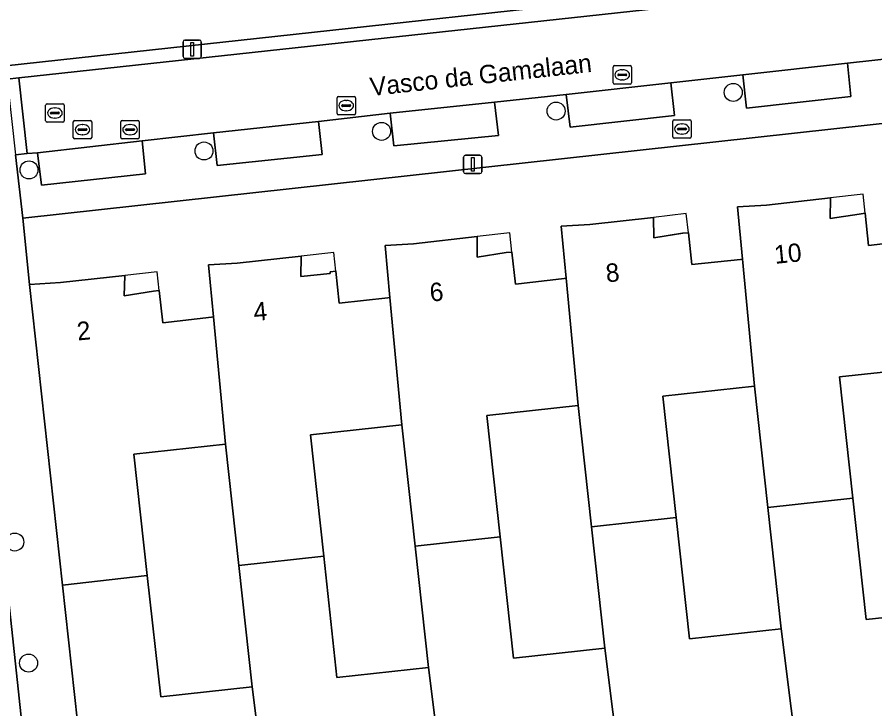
# Model space of a CAD drawing. Extents: x 161248 to 161848, y 384871 to 385383.
# Drawn here: x 161347.65 to 161394.3, y 385074.55 to 385112.17 of the extents above; entities that cross this region are included whole.
import ezdxf

# ---------------------------------------------------------------- set-up
doc = ezdxf.new("R2010")
doc.units = 0
for name, color, linetype in [('IMGEO_Boom', 7, 'Continuous'), ('IMGEO_Brandkraan', 7, 'Continuous'), ('IMGEO_Erf', 7, 'Continuous'), ('IMGEO_Kolk', 7, 'Continuous'), ('IMGEO_Lichtmast', 7, 'Continuous'), ('IMGEO_Openbare_ruimte_label', 7, 'Continuous'), ('IMGEO_Pand', 7, 'Continuous'), ('IMGEO_Pand_nummerreeks', 7, 'Continuous'), ('IMGEO_Pand_overbouw', 7, 'Continuous'), ('IMGEO_Parkeervlak_open', 7, 'Continuous'), ('IMGEO_Rijbaan_lokaal_open', 7, 'Continuous'), ('IMGEO_Rioolput', 7, 'Continuous'), ('IMGEO_Voetpad_open', 7, 'Continuous')]:
    doc.layers.add(name, color=color, linetype=linetype)

msp = doc.modelspace()

# ---------------------------------------------------------------- linework, layer by layer
at = {"layer": 'IMGEO_Boom'}
for centre in [(161386.594, 385108.08), (161376.963, 385107.067), (161367.474, 385105.962), (161357.815, 385104.894), (161348.299, 385103.866), (161347.527, 385083.626), (161348.275, 385077.04)]:
    msp.add_circle(centre, 0.489, dxfattribs=at)
at = {"layer": 'IMGEO_Brandkraan'}
for p, q in [((161383.303, 385105.663), (161383.303, 385106.515)), ((161383.378, 385106.589), (161384.23, 385106.589)), ((161384.304, 385106.515), (161384.304, 385105.663)), ((161383.562, 385106.083), (161383.562, 385106.095)), ((161384, 385106.046), (161383.602, 385106.046)), ((161383.605, 385106.132), (161384.003, 385106.132)), ((161383.791, 385106.369), (161383.816, 385106.369)), ((161384.046, 385106.095), (161384.046, 385106.083)), ((161384.23, 385105.589), (161383.378, 385105.589)), ((161383.814, 385105.809), (161383.789, 385105.809))]:
    msp.add_line(p, q, dxfattribs=at)
for points in [[(161383.303, 385105.663), (161383.303, 385106.515)], [(161383.378, 385106.589), (161384.23, 385106.589)], [(161384.304, 385106.515), (161384.304, 385105.663)], [(161384.23, 385105.589), (161383.378, 385105.589)]]:
    msp.add_lwpolyline(points, dxfattribs=at)
for centre, radius, start, end in [((161383.38, 385106.513), 0.0765, 91.552, 178.448), ((161383.38, 385106.513), 0.0765, 91.552, 178.448), ((161384.228, 385106.513), 0.0765, 1.552, 88.448), ((161384.228, 385106.513), 0.0765, 1.552, 88.448), ((161383.602, 385106.092), 0.0403, 85.8775, 175.7526), ((161383.599, 385106.082), 0.0366, 178.938, 274.7102), ((161384.003, 385106.089), 0.043, 264.8664, 352.4533), ((161384.007, 385106.094), 0.0386, 1.7309, 96.639), ((161383.38, 385105.665), 0.0765, 181.552, 268.448), ((161383.38, 385105.665), 0.0765, 181.552, 268.448), ((161384.228, 385105.665), 0.0765, 271.552, 358.448), ((161384.228, 385105.665), 0.0765, 271.552, 358.448)]:
    msp.add_arc(centre, radius, start, end, dxfattribs=at)
for centre, major_axis, ratio, start_param, end_param in [((161383.79, 385106.089), (-0.387, 0.002), 0.722429, 4.712389, 7.853982), ((161383.815, 385106.089), (-0.39, 0.002), 0.717154, 1.570796, 4.712389)]:
    msp.add_ellipse(centre, major_axis=major_axis, ratio=ratio, start_param=start_param, end_param=end_param, dxfattribs=at)
at = {"layer": 'IMGEO_Erf'}
for points in [[(161346.621, 385113.155), (161347.043, 385109.527), (161395.24, 385114.796)], [(161396.177, 385106.561), (161347.958, 385101.247), (161348.324, 385097.628), (161350.02, 385097.735), (161353.505, 385098.125), (161353.479, 385097.007), (161355.064, 385097.262), (161355.384, 385097.3), (161355.582, 385095.542), (161358.216, 385095.855), (161358.329, 385095.868), (161358.064, 385098.701), (161359.617, 385098.791), (161363.102, 385099.18), (161363.085, 385098.066), (161364.68, 385098.223), (161364.67, 385098.325), (161364.982, 385098.356), (161365.171, 385096.619), (161367.817, 385096.913), (161367.93, 385096.926), (161367.668, 385099.753), (161369.2, 385099.839), (161372.675, 385100.238), (161372.675, 385100.219), (161372.674, 385099.12), (161374.239, 385099.377), (161374.563, 385099.398), (161374.763, 385097.649), (161374.919, 385097.667), (161377.249, 385097.943), (161377.398, 385097.961), (161377.511, 385097.974), (161377.246, 385100.811), (161378.806, 385100.893), (161382.257, 385101.285), (161382.274, 385100.174), (161383.835, 385100.418), (161384.156, 385100.449), (161384.347, 385098.716), (161386.986, 385099.001), (161387.099, 385099.013), (161386.833, 385101.856), (161388.402, 385101.946), (161391.885, 385102.341), (161391.863, 385101.222), (161393.446, 385101.462), (161393.768, 385101.507), (161393.957, 385099.746), (161396.893, 385100.095)]]:
    msp.add_lwpolyline(points, dxfattribs=at)
for points in [[(161397.643, 385093.177), (161392.383, 385092.607), (161393.106, 385086.007), (161393.83, 385079.404), (161399.089, 385079.976)], [(161387.745, 385092.1), (161382.774, 385091.556), (161383.499, 385084.956), (161384.225, 385078.353), (161389.196, 385078.897), (161388.471, 385085.497)], [(161378.883, 385084.458), (161378.158, 385091.05), (161373.188, 385090.506), (161373.914, 385083.906), (161374.64, 385077.304), (161379.61, 385077.848)], [(161368.572, 385090.002), (161363.603, 385089.458), (161364.324, 385082.857), (161365.046, 385076.254), (161370.015, 385076.798), (161369.294, 385083.399)], [(161354.733, 385081.808), (161355.46, 385075.205), (161360.431, 385075.749), (161359.704, 385082.348), (161358.976, 385088.951), (161354.006, 385088.408)]]:
    msp.add_lwpolyline(points, close=True, dxfattribs=at)
at = {"layer": 'IMGEO_Kolk'}
for p, q in [((161380.058, 385108.61), (161380.058, 385109.462)), ((161380.133, 385109.536), (161380.985, 385109.536)), ((161380.546, 385109.316), (161380.571, 385109.316)), ((161381.059, 385109.462), (161381.059, 385108.61)), ((161380.317, 385109.03), (161380.317, 385109.042)), ((161380.755, 385108.993), (161380.357, 385108.993)), ((161380.36, 385109.079), (161380.758, 385109.079)), ((161380.801, 385109.042), (161380.801, 385109.03)), ((161380.985, 385108.536), (161380.133, 385108.536)), ((161380.569, 385108.756), (161380.544, 385108.756)), ((161365.048, 385106.937), (161365.048, 385107.789)), ((161365.123, 385107.863), (161365.975, 385107.863)), ((161365.536, 385107.643), (161365.561, 385107.643)), ((161366.049, 385107.789), (161366.049, 385106.937)), ((161365.307, 385107.357), (161365.307, 385107.369)), ((161365.745, 385107.32), (161365.347, 385107.32)), ((161365.35, 385107.406), (161365.748, 385107.406)), ((161365.559, 385107.083), (161365.534, 385107.083)), ((161365.791, 385107.369), (161365.791, 385107.357)), ((161353.371, 385106.555), (161354.223, 385106.555)), ((161365.975, 385106.863), (161365.123, 385106.863)), ((161353.296, 385105.629), (161353.296, 385106.481)), ((161353.555, 385106.049), (161353.555, 385106.061)), ((161353.598, 385106.098), (161353.996, 385106.098)), ((161353.784, 385106.335), (161353.809, 385106.335)), ((161354.039, 385106.061), (161354.039, 385106.049)), ((161354.297, 385106.481), (161354.297, 385105.629)), ((161354.223, 385105.555), (161353.371, 385105.555)), ((161353.993, 385106.012), (161353.595, 385106.012)), ((161353.807, 385105.775), (161353.782, 385105.775))]:
    msp.add_line(p, q, dxfattribs=at)
for points in [[(161380.058, 385108.61), (161380.058, 385109.462)], [(161380.133, 385109.536), (161380.985, 385109.536)], [(161381.059, 385109.462), (161381.059, 385108.61)], [(161380.985, 385108.536), (161380.133, 385108.536)], [(161365.048, 385106.937), (161365.048, 385107.789)], [(161365.123, 385107.863), (161365.975, 385107.863)], [(161366.049, 385107.789), (161366.049, 385106.937)], [(161353.371, 385106.555), (161354.223, 385106.555)], [(161365.975, 385106.863), (161365.123, 385106.863)], [(161353.296, 385105.629), (161353.296, 385106.481)], [(161354.297, 385106.481), (161354.297, 385105.629)], [(161354.223, 385105.555), (161353.371, 385105.555)]]:
    msp.add_lwpolyline(points, dxfattribs=at)
for centre, radius, start, end in [((161380.135, 385109.46), 0.0765, 91.552, 178.448), ((161380.135, 385109.46), 0.0765, 91.552, 178.448), ((161380.983, 385109.46), 0.0765, 1.552, 88.448), ((161380.983, 385109.46), 0.0765, 1.552, 88.448), ((161380.357, 385109.039), 0.0403, 85.8775, 175.7526), ((161380.354, 385109.029), 0.0366, 178.938, 274.7102), ((161380.758, 385109.036), 0.043, 264.8664, 352.4533), ((161380.762, 385109.041), 0.0386, 1.7309, 96.639), ((161380.135, 385108.612), 0.0765, 181.552, 268.448), ((161380.135, 385108.612), 0.0765, 181.552, 268.448), ((161380.983, 385108.612), 0.0765, 271.552, 358.448), ((161380.983, 385108.612), 0.0765, 271.552, 358.448), ((161365.125, 385107.787), 0.0765, 91.552, 178.448), ((161365.125, 385107.787), 0.0765, 91.552, 178.448), ((161365.973, 385107.787), 0.0765, 1.552, 88.448), ((161365.973, 385107.787), 0.0765, 1.552, 88.448), ((161365.347, 385107.366), 0.0403, 85.8775, 175.7526), ((161365.344, 385107.356), 0.0366, 178.938, 274.7102), ((161365.748, 385107.363), 0.043, 264.8664, 352.4533), ((161365.752, 385107.368), 0.0386, 1.7309, 96.639), ((161353.373, 385106.479), 0.0765, 91.552, 178.448), ((161353.373, 385106.479), 0.0765, 91.552, 178.448), ((161354.221, 385106.479), 0.0765, 1.552, 88.448), ((161354.221, 385106.479), 0.0765, 1.552, 88.448), ((161365.125, 385106.939), 0.0765, 181.552, 268.448), ((161365.125, 385106.939), 0.0765, 181.552, 268.448), ((161365.973, 385106.939), 0.0765, 271.552, 358.448), ((161365.973, 385106.939), 0.0765, 271.552, 358.448), ((161353.595, 385106.058), 0.0403, 85.8775, 175.7526), ((161353.592, 385106.048), 0.0366, 178.938, 274.7102), ((161353.996, 385106.055), 0.043, 264.8664, 352.4533), ((161354, 385106.06), 0.0386, 1.7309, 96.639), ((161353.373, 385105.631), 0.0765, 181.552, 268.448), ((161353.373, 385105.631), 0.0765, 181.552, 268.448), ((161354.221, 385105.631), 0.0765, 271.552, 358.448), ((161354.221, 385105.631), 0.0765, 271.552, 358.448)]:
    msp.add_arc(centre, radius, start, end, dxfattribs=at)
for centre, major_axis, ratio, start_param, end_param in [((161380.545, 385109.036), (-0.387, 0.002), 0.722429, 4.712389, 7.853982), ((161380.57, 385109.036), (-0.39, 0.002), 0.717154, 1.570796, 4.712389), ((161365.535, 385107.363), (-0.387, 0.002), 0.722429, 4.712389, 7.853982), ((161365.56, 385107.363), (-0.39, 0.002), 0.717154, 1.570796, 4.712389), ((161353.783, 385106.055), (-0.387, 0.002), 0.722429, 4.712389, 7.853982), ((161353.808, 385106.055), (-0.39, 0.002), 0.717154, 1.570796, 4.712389)]:
    msp.add_ellipse(centre, major_axis=major_axis, ratio=ratio, start_param=start_param, end_param=end_param, dxfattribs=at)
at = {"layer": 'IMGEO_Lichtmast'}
for p, q in [((161356.68, 385110.027), (161356.68, 385110.827)), ((161356.68, 385110.827), (161356.68, 385110.027)), ((161356.78, 385110.927), (161357.57, 385110.927)), ((161357.57, 385110.927), (161356.78, 385110.927)), ((161357.67, 385110.827), (161357.67, 385110.027)), ((161357.67, 385110.027), (161357.67, 385110.827)), ((161357.57, 385109.927), (161356.78, 385109.927)), ((161356.78, 385109.927), (161357.57, 385109.927)), ((161372.034, 385104.664), (161372.824, 385104.664)), ((161372.824, 385104.664), (161372.034, 385104.664)), ((161371.934, 385103.764), (161371.934, 385104.564)), ((161371.934, 385104.564), (161371.934, 385103.764)), ((161372.924, 385104.564), (161372.924, 385103.764)), ((161372.924, 385103.764), (161372.924, 385104.564)), ((161372.824, 385103.664), (161372.034, 385103.664)), ((161372.034, 385103.664), (161372.824, 385103.664))]:
    msp.add_line(p, q, dxfattribs=at)
for points in [[(161357.1, 385110.802), (161357.25, 385110.802), (161357.25, 385110.052), (161357.1, 385110.052), (161357.1, 385110.802)], [(161372.354, 385104.539), (161372.504, 385104.539), (161372.504, 385103.789), (161372.354, 385103.789), (161372.354, 385104.539)]]:
    msp.add_lwpolyline(points, dxfattribs=at)
for centre, start, end in [((161356.78, 385110.827), 90, 180), ((161356.78, 385110.827), 90, 180), ((161357.57, 385110.827), 0, 90), ((161357.57, 385110.827), 360, 90), ((161356.78, 385110.027), 180, 270), ((161356.78, 385110.027), 180, 270), ((161357.57, 385110.027), 270, 0), ((161357.57, 385110.027), 270, 0), ((161372.034, 385104.564), 90, 180), ((161372.034, 385104.564), 90, 180), ((161372.824, 385104.564), 0, 90), ((161372.824, 385104.564), 360, 90), ((161372.034, 385103.764), 180, 270), ((161372.034, 385103.764), 180, 270), ((161372.824, 385103.764), 270, 0), ((161372.824, 385103.764), 270, 0)]:
    msp.add_arc(centre, 0.1, start, end, dxfattribs=at)
at = {"layer": 'IMGEO_Pand'}
for points in [[(161396.893, 385100.095), (161393.957, 385099.746), (161393.768, 385101.507), (161393.446, 385101.462), (161391.863, 385101.222), (161391.885, 385102.341), (161388.402, 385101.946), (161386.833, 385101.856), (161387.099, 385099.013), (161387.745, 385092.1), (161388.471, 385085.497), (161393.106, 385086.007), (161392.383, 385092.607), (161397.643, 385093.177)], [(161387.099, 385099.013), (161386.986, 385099.001), (161384.347, 385098.716), (161384.156, 385100.449), (161383.835, 385100.418), (161382.274, 385100.174), (161382.257, 385101.285), (161378.806, 385100.893), (161377.246, 385100.811), (161377.511, 385097.974), (161378.158, 385091.05), (161378.883, 385084.458), (161383.499, 385084.956), (161382.774, 385091.556), (161387.745, 385092.1)], [(161377.511, 385097.974), (161377.398, 385097.961), (161377.249, 385097.943), (161374.919, 385097.667), (161374.763, 385097.649), (161374.563, 385099.398), (161374.239, 385099.377), (161372.674, 385099.12), (161372.675, 385100.219), (161372.675, 385100.238), (161369.2, 385099.839), (161367.668, 385099.753), (161367.93, 385096.926), (161368.572, 385090.002), (161369.294, 385083.399), (161373.914, 385083.906), (161373.188, 385090.506), (161378.158, 385091.05)], [(161367.93, 385096.926), (161367.817, 385096.913), (161365.171, 385096.619), (161364.982, 385098.356), (161364.67, 385098.325), (161364.68, 385098.223), (161363.085, 385098.066), (161363.102, 385099.18), (161359.617, 385098.791), (161358.064, 385098.701), (161358.329, 385095.868), (161358.976, 385088.951), (161359.704, 385082.348), (161364.324, 385082.857), (161363.603, 385089.458), (161368.572, 385090.002)], [(161358.329, 385095.868), (161358.216, 385095.855), (161355.582, 385095.542), (161355.384, 385097.3), (161355.064, 385097.262), (161353.479, 385097.007), (161353.505, 385098.125), (161350.02, 385097.735), (161348.324, 385097.628), (161350.119, 385081.284), (161354.733, 385081.808), (161354.006, 385088.408), (161358.976, 385088.951)], [(161399.089, 385079.976), (161393.83, 385079.404), (161393.106, 385086.007), (161388.471, 385085.497), (161389.196, 385078.897), (161390.289, 385070.246), (161390.427, 385069.158), (161391.989, 385069.316), (161395.445, 385069.768), (161395.185, 385070.855), (161396.756, 385071.044), (161397.105, 385070.988), (161396.909, 385072.725), (161399.84, 385073.078)], [(161389.196, 385078.897), (161384.225, 385078.353), (161383.499, 385084.956), (161378.883, 385084.458), (161379.61, 385077.848), (161380.486, 385070.921), (161380.842, 385068.105), (161382.387, 385068.277), (161385.852, 385068.735), (161385.596, 385069.808), (161387.187, 385069.987), (161387.506, 385069.939), (161390.152, 385070.231), (161390.289, 385070.246)], [(161379.61, 385077.848), (161374.64, 385077.304), (161373.914, 385083.906), (161369.294, 385083.399), (161370.015, 385076.798), (161371.106, 385068.129), (161371.242, 385067.048), (161372.789, 385067.223), (161376.26, 385067.675), (161376.01, 385068.756), (161377.597, 385068.925), (161377.919, 385068.889), (161377.734, 385070.637), (161380.373, 385070.909), (161380.486, 385070.921)], [(161370.015, 385076.798), (161365.046, 385076.254), (161364.324, 385082.857), (161359.704, 385082.348), (161360.431, 385075.749), (161361.306, 385068.843), (161361.665, 385066.004), (161363.208, 385066.176), (161366.667, 385066.632), (161366.42, 385067.711), (161368.015, 385067.887), (161368.329, 385067.844), (161370.967, 385068.115), (161371.106, 385068.129)], [(161360.431, 385075.749), (161355.46, 385075.205), (161354.733, 385081.808), (161350.119, 385081.284), (161351.915, 385064.931), (161353.62, 385065.114), (161357.09, 385065.569), (161356.831, 385066.667), (161358.411, 385066.845), (161358.738, 385066.796), (161358.539, 385068.524), (161361.193, 385068.83), (161361.306, 385068.843)]]:
    msp.add_lwpolyline(points, close=True, dxfattribs=at)
at = {"layer": 'IMGEO_Pand_overbouw'}
for points in [[(161393.657, 385102.542), (161391.885, 385102.341), (161391.863, 385101.222), (161393.446, 385101.462), (161393.768, 385101.507)], [(161384.041, 385101.488), (161382.257, 385101.285), (161382.274, 385100.174), (161383.849, 385100.419), (161384.156, 385100.449)], [(161374.444, 385100.441), (161372.675, 385100.238), (161372.674, 385099.12), (161374.239, 385099.377), (161374.563, 385099.398)], [(161364.871, 385099.377), (161363.102, 385099.18), (161363.085, 385098.066), (161364.68, 385098.223), (161364.67, 385098.325), (161364.982, 385098.356)], [(161355.269, 385098.322), (161353.505, 385098.125), (161353.479, 385097.007), (161355.064, 385097.262), (161355.384, 385097.3)]]:
    msp.add_lwpolyline(points, close=True, dxfattribs=at)
at = {"layer": 'IMGEO_Parkeervlak_open'}
for points in [[(161387.116, 385109.034), (161387.313, 385107.226), (161392.995, 385107.862), (161392.803, 385109.668)], [(161377.519, 385107.972), (161377.721, 385106.189), (161383.406, 385106.819), (161383.208, 385108.61)], [(161373.62, 385107.557), (161367.933, 385106.944), (161368.134, 385105.166), (161373.825, 385105.741)], [(161358.333, 385105.878), (161358.539, 385104.107), (161364.238, 385104.702), (161364.034, 385106.491)], [(161354.446, 385105.455), (161348.755, 385104.797), (161348.975, 385103.03), (161354.642, 385103.658)]]:
    msp.add_lwpolyline(points, close=True, dxfattribs=at)
at = {"layer": 'IMGEO_Rijbaan_lokaal_open'}
for points in [[(161392.803, 385109.668), (161395.787, 385109.99), (161397.29, 385110.152), (161396.837, 385114.227), (161395.323, 385114.062), (161347.74, 385108.882), (161348.197, 385104.749), (161348.755, 385104.797), (161354.446, 385105.455), (161358.333, 385105.878), (161364.034, 385106.491), (161367.933, 385106.944), (161373.62, 385107.557), (161377.519, 385107.972), (161383.208, 385108.61), (161387.116, 385109.034)], [(161348.197, 385104.749), (161347.74, 385108.882), (161347.116, 385108.799), (161347.569, 385104.681)]]:
    msp.add_lwpolyline(points, close=True, dxfattribs=at)
msp.add_lwpolyline([(161338.624, 385041.3), (161357.909, 385047.41), (161357.367, 385047.297), (161356.818, 385047.234), (161356.265, 385047.219), (161355.714, 385047.255), (161355.167, 385047.339), (161354.63, 385047.472), (161354.108, 385047.652), (161353.603, 385047.878), (161353.121, 385048.149), (161352.665, 385048.461), (161352.238, 385048.813), (161351.845, 385049.202), (161351.488, 385049.624), (161351.17, 385050.076), (161350.893, 385050.555), (161350.661, 385051.057), (161350.474, 385051.578), (161350.335, 385052.113), (161350.244, 385052.658), (161350.213, 385052.904), (161348.495, 385068.357), (161346.704, 385084.797)], dxfattribs=at)
at = {"layer": 'IMGEO_Rioolput'}
for p, q in [((161349.28, 385107.459), (161350.132, 385107.459)), ((161349.205, 385106.533), (161349.205, 385107.385)), ((161349.464, 385106.953), (161349.464, 385106.965)), ((161349.507, 385107.002), (161349.905, 385107.002)), ((161349.693, 385107.239), (161349.718, 385107.239)), ((161349.948, 385106.965), (161349.948, 385106.953)), ((161350.206, 385107.385), (161350.206, 385106.533)), ((161349.902, 385106.916), (161349.504, 385106.916)), ((161349.716, 385106.679), (161349.691, 385106.679)), ((161350.782, 385106.553), (161351.634, 385106.553)), ((161350.132, 385106.459), (161349.28, 385106.459)), ((161350.707, 385105.627), (161350.707, 385106.479)), ((161350.966, 385106.047), (161350.966, 385106.059)), ((161351.009, 385106.096), (161351.407, 385106.096)), ((161351.195, 385106.333), (161351.22, 385106.333)), ((161351.45, 385106.059), (161351.45, 385106.047)), ((161351.708, 385106.479), (161351.708, 385105.627)), ((161351.634, 385105.553), (161350.782, 385105.553)), ((161351.404, 385106.01), (161351.006, 385106.01)), ((161351.218, 385105.773), (161351.193, 385105.773))]:
    msp.add_line(p, q, dxfattribs=at)
for points in [[(161349.28, 385107.459), (161350.132, 385107.459)], [(161349.205, 385106.533), (161349.205, 385107.385)], [(161350.206, 385107.385), (161350.206, 385106.533)], [(161350.782, 385106.553), (161351.634, 385106.553)], [(161350.132, 385106.459), (161349.28, 385106.459)], [(161350.707, 385105.627), (161350.707, 385106.479)], [(161351.708, 385106.479), (161351.708, 385105.627)], [(161351.634, 385105.553), (161350.782, 385105.553)]]:
    msp.add_lwpolyline(points, dxfattribs=at)
for centre, radius, start, end in [((161349.282, 385107.383), 0.0765, 91.552, 178.448), ((161349.282, 385107.383), 0.0765, 91.552, 178.448), ((161350.13, 385107.383), 0.0765, 1.552, 88.448), ((161350.13, 385107.383), 0.0765, 1.552, 88.448), ((161349.504, 385106.962), 0.0403, 85.8775, 175.7526), ((161349.501, 385106.952), 0.0366, 178.938, 274.7102), ((161349.905, 385106.959), 0.043, 264.8664, 352.4533), ((161349.909, 385106.964), 0.0386, 1.7309, 96.639), ((161349.282, 385106.535), 0.0765, 181.552, 268.448), ((161349.282, 385106.535), 0.0765, 181.552, 268.448), ((161350.13, 385106.535), 0.0765, 271.552, 358.448), ((161350.13, 385106.535), 0.0765, 271.552, 358.448), ((161350.784, 385106.477), 0.0765, 91.552, 178.448), ((161350.784, 385106.477), 0.0765, 91.552, 178.448), ((161351.632, 385106.477), 0.0765, 1.552, 88.448), ((161351.632, 385106.477), 0.0765, 1.552, 88.448), ((161351.006, 385106.056), 0.0403, 85.8775, 175.7526), ((161351.003, 385106.046), 0.0366, 178.938, 274.7102), ((161351.407, 385106.053), 0.043, 264.8664, 352.4533), ((161351.411, 385106.058), 0.0386, 1.7309, 96.639), ((161350.784, 385105.629), 0.0765, 181.552, 268.448), ((161350.784, 385105.629), 0.0765, 181.552, 268.448), ((161351.632, 385105.629), 0.0765, 271.552, 358.448), ((161351.632, 385105.629), 0.0765, 271.552, 358.448)]:
    msp.add_arc(centre, radius, start, end, dxfattribs=at)
for centre, major_axis, ratio, start_param, end_param in [((161349.692, 385106.959), (-0.387, 0.002), 0.722429, 4.712389, 7.853982), ((161349.717, 385106.959), (-0.39, 0.002), 0.717154, 1.570796, 4.712389), ((161351.194, 385106.053), (-0.387, 0.002), 0.722429, 4.712389, 7.853982), ((161351.219, 385106.053), (-0.39, 0.002), 0.717154, 1.570796, 4.712389)]:
    msp.add_ellipse(centre, major_axis=major_axis, ratio=ratio, start_param=start_param, end_param=end_param, dxfattribs=at)
at = {"layer": 'IMGEO_Voetpad_open'}
msp.add_lwpolyline([(161395.323, 385114.062), (161395.24, 385114.796), (161347.043, 385109.527), (161347.116, 385108.799), (161347.74, 385108.882)], close=True, dxfattribs=at)
for points in [[(161395.787, 385109.99), (161392.803, 385109.668), (161392.995, 385107.862), (161387.313, 385107.226), (161387.116, 385109.034), (161383.208, 385108.61), (161383.406, 385106.819), (161377.721, 385106.189), (161377.519, 385107.972), (161373.62, 385107.557), (161373.825, 385105.741), (161368.134, 385105.166), (161367.933, 385106.944), (161364.034, 385106.491), (161364.238, 385104.702), (161358.539, 385104.107), (161358.333, 385105.878), (161354.446, 385105.455), (161354.642, 385103.658), (161348.975, 385103.03), (161348.755, 385104.797), (161348.197, 385104.749), (161347.569, 385104.681), (161347.958, 385101.247), (161396.177, 385106.561)], [(161351.915, 385064.931), (161350.119, 385081.284), (161348.324, 385097.628), (161347.958, 385101.247), (161347.569, 385104.681)], [(161346.704, 385084.797), (161348.495, 385068.357)]]:
    msp.add_lwpolyline(points, dxfattribs=at)

# ---------------------------------------------------------------- texts
at = {"layer": 'IMGEO_Openbare_ruimte_label'}
msp.add_text('Vasco da Gamalaan', height=1, rotation=6.2579, dxfattribs=at).set_placement((161366.899, 385107.879))
at = {"layer": 'IMGEO_Pand_nummerreeks'}
for s, rotation, p in [('10', 5.5061, (161388.872, 385098.755)), ('8', 5.4316, (161379.709, 385097.748)), ('6', 5.552, (161370.136, 385096.696)), ('4', 5.4546, (161360.552, 385095.642)), ('2', 5.4775, (161350.951, 385094.584))]:
    msp.add_text(s, height=1, rotation=rotation, dxfattribs=at).set_placement(p)

doc.saveas('drawing.dxf')
